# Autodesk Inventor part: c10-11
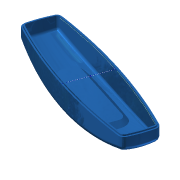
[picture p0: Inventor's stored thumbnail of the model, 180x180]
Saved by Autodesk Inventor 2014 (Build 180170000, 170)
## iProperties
Created: 2010-12
Part Number: c10-11
Material: Generic
Document SubType Name: Modeling
Designer: Thom Tremblay
Density: 1 g/cm^3
Appearance: Generic
Author: Thom Tremblay
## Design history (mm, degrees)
sketch "Sketch1"
  geometry: L1 (-60, -12)-(60, -12); L2 (60, -12)-(60, 12); L3 (60, 12)-(-60, 12); L4 (-60, 12)-(-60, -12); A1 r 350 centre (0, -332.819) between (60, 12) and (-60, 12); A2 r 350 centre (0, 332.819) between (-60, -12) and (60, -12); 3 further points
  constraints: 8 end point, 4 point on circle, 2 centre point, 2 midpoint, 2 parallel, 1 equal radius, 1 horizontal, 1 horizontal alignment, 1 perpendicular, 1 vertical alignment
  dimensions: "d0" = 120 distance of L3.end L2.end; "d1" = 24 distance of L2.end L1.end; "d2" = 350 radius of A1
workplane "Work Plane4"
sketch "Sketch5"
  geometry: L1 (-60, 12)-(-60, -12) reference; L2 (60, -12)-(60, 12) reference; L3 (-58, 10.314)-(-58, -10.314); L4 (58, -10.314)-(58, 10.314); A1 r 350 centre (0, 332.819) between (-60, -12) and (60, -12) reference; A2 r 350 centre (0, -332.819) between (60, 12) and (-60, 12) reference; A3 r 348 centre (0, 332.819) between (-58, -10.314) and (58, -10.314); A4 r 348 centre (0, -332.819) between (58, 10.314) and (-58, 10.314); 1 further point
  constraints: 4 end point, 4 point on circle, 2 centre point, 3 other
  dimensions: "d37" = 2 distance between parallel lines of L2 L4
sketch "Sketch6"
  geometry: L1 (-60, 0)-(60, 0); L2 (60, 0)-(58.843, 22.085); L3 (-60, 0)-(-58.779, 23.307); A1 r 691.758 centre (630.81, -36.204) between (-60, 0) and (-58, -100); A2 r 691.758 centre (-630.81, -36.204) between (58, -100) and (60, 0); 1 further point
  constraints: 6 end point, 4 point on circle, 2 centre point, 2 tangent, 1 horizontal
  dimensions: "d53" = 87 deg angle of L1 L3; "d54" = 87 deg angle of L1 L2 (= d53)
sketch "Sketch7"
  geometry: L1 (17.181, 0)-(12, 0) reference; L2 (15.181, -100)-(10.314, -100) reference; L3 (17.181, 0)-(16.768, 11.838); A1 r 911.322 centre (-893.585, -31.805) between (15.181, -100) and (17.181, 0); 1 further point
  constraints: 2 end point, 2 point on circle, 1 centre point, 1 tangent
  dimensions: "d56" = 88 deg angle of L1 L3
feature "LoftSrf2" sketch "Sketch5", "Sketch6", "Sketch7" dims "d57" = 0, "d58" = 90 deg, "d59" = 0, "d60" = 90 deg, "d61" = 0, "d62" = 90 deg, "d63" = 0, "d64" = 90 deg, "d65" = 0, "d66" = 90 deg
sketch "Sketch2"
  geometry: L1 (-75, -16)-(75, -16); L2 (-75, -60)-(75, -60); A1 r 183.781 centre (0, -183.781) between (75, -16) and (-75, -16); 2 further points
  constraints: 4 end point, 3 point on circle, 1 centre point, 1 coincident, 1 horizontal, 1 parallel
  dimensions: "d5" = 16 distance from line of point (0, 0) L1; "d7" = 60 distance from line of point (0, 0) L2; "d55" = 150 distance of L1.start L1.end
feature "RevolutionSrf1" sketch "Sketch2" dims angle "d8" = 40 deg
patch "Boundary Patch1" dims "d13" = 0, "d67" = 0, "d68" = 0, "d69" = 0, "d70" = 0
workplane "Work Plane1"
sketch "Sketch3"
  geometry: L1 (52, -85)-(52, -73); L2 (38, -73)-(38, -85); A1 r 7 centre (45, -73) between (52, -73) and (38, -73); A2 r 7 centre (45, -85) between (38, -85) and (52, -85); 1 further point
  constraints: 4 end point, 4 point on circle, 4 tangent, 2 centre point, 1 parallel, 1 vertical
  dimensions: "d15" = 12 distance of L1.start L1.end; "d16" = 7 radius of A1; "d50" = 45 horizontal distance of A1.centre point (0, 0); "d51" = 85 vertical distance of point (0, 0) A2.centre
extrude_surface "ExtrusionSrf2" sketch "Sketch3" dims "d19" = 14, "d20" = 5 deg
pattern_linear "Rectangular Pattern1" dims "d23" = 90
workplane "Work Plane2"
feature "Sculpt1"
sketch "Sketch4"
  geometry: L1 (-24.5, 6)-(24.5, 6); L2 (27.5, 3)-(27.5, -3); L3 (24.5, -6)-(-24.5, -6); L4 (-27.5, -3)-(-27.5, 3); A1 r 3 centre (-24.5, 3) between (-24.5, 6) and (-27.5, 3); A2 r 3 centre (24.5, 3) between (27.5, 3) and (24.5, 6); A3 r 3 centre (24.5, -3) between (24.5, -6) and (27.5, -3); A4 r 3 centre (-24.5, -3) between (-27.5, -3) and (-24.5, -6); 6 further points
  constraints: 8 end point, 8 point on circle, 8 tangent, 6 point on line, 4 centre point, 3 equal radius, 2 midpoint, 2 parallel, 1 horizontal, 1 horizontal alignment, 1 perpendicular, 1 vertical alignment
  dimensions: "d28" = 55 distance of point (27.5, -6) point (-27.5, -6); "d29" = 12 distance of point (27.5, 6) point (27.5, -6); "d30" = 3 radius of A1
extrude_surface "ExtrusionSrf6" sketch "Sketch4" dims "d31" = 14, "d32" = 45 deg
patch "Boundary Patch2" dims "d33" = 0, "d34" = 0
fillet "Fillet1" dims "d79" = 4, "d80" = 3, "d81" = 1
feature "Sculpt2"
node "Splitting Plane 1"
shell "Shell1" dims "d83" = 2
split "Split1"
  body "Solid1"
feature "Lip1" dims "d188" = 1, "d189" = 1, "d190" = 0, "d191" = 0, "d192" = 0, "d193" = 0
feature "Lip2" dims "d194" = 1, "d195" = 1, "d196" = 0, "d197" = 0, "d198" = 0, "d199" = 0.5
split "Split3"
  node "Back"
sketch "Sketch9"
  geometry: L1 (50.167, -73)-(50.167, -85) reference; L2 (39.833, -85)-(39.833, -73) reference; L3 (45, -73)-(45, -85); L4 (45, -85)-(39.833, -85); A1 r 5.167 centre (45, -73) between (50.167, -73) and (39.833, -73) reference; A2 r 5.167 centre (45, -85) between (39.833, -85) and (50.167, -85) reference; 5 further points
  constraints: 4 end point, 1 horizontal, 1 midpoint, 1 parallel, 1 perpendicular, 1 vertical, 3 other
  dimensions: "d86" = 90 distance of point (45, -79) point (-45, -79); "d89" = 40 distance of point (45, -79) point (45, -39)
  node "Projected Loop1"
feature "Boss1" dims "d92" = 0, "d93" = 0, "d94" = 7, "d95" = 2, "d96" = 0.5, "d97" = 6, "d98" = 1.25, "d99" = 3.5, "d100" = 2.5 deg, "d101" = 2.5 deg, "d102" = 2.5 deg, "d103" = 2.5 deg, "d104" = 90 deg, "d107" = 2, "d108" = 2, "d109" = 10, "d110" = 0, "d111" = 10 deg, "d112" = 2.5 deg, "d113" = 0, "d114" = 0, "d115" = 0, "d116" = 360 deg
feature "Boss2" dims "d117" = 3, "d118" = 0, "d119" = 6, "d120" = 3, "d121" = 9.5, "d122" = 2 deg, "d123" = 1 deg, "d126" = 2, "d127" = 2, "d128" = 10, "d129" = 0, "d130" = 10 deg, "d131" = 2.5 deg, "d132" = 0, "d133" = 0, "d134" = 0, "d135" = 360 deg
workplane "Work Plane6"
sketch "Sketch10"
  geometry: L1 (24, -85)-(-24, -85); L2 (-30, -79)-(-30, -51); L3 (-24, -45)-(24, -45); L4 (30, -51)-(30, -79); L5 (54.344, -100)-(-54.344, -100) reference; A1 r 6 centre (-24, -51) between (-24, -45) and (-30, -51); A2 r 6 centre (24, -51) between (30, -51) and (24, -45); A3 r 6 centre (24, -79) between (24, -85) and (30, -79); A4 r 6 centre (-24, -79) between (-30, -79) and (-24, -85); 5 further points
  constraints: 8 end point, 8 point on circle, 8 tangent, 6 point on line, 4 centre point, 3 equal radius, 2 parallel, 1 horizontal, 1 midpoint, 1 perpendicular, 1 vertical alignment
  dimensions: "d137" = 60 distance of point (-30, -45) point (30, -45); "d138" = 40 distance of point (-30, -85) point (-30, -45); "d139" = 15 distance between parallel lines of L5 L1; "d141" = 6 radius of A2
feature "Rest1" sketch "Sketch10" dims "d142" = 5, "d143" = 0, "d144" = 0, "d145" = 0, "d146" = 2 deg, "d147" = 2 deg, "d148" = 2
feature "Rule Fillet1" dims "d149" = 2, "d150" = 1
workplane "Work Plane7"
sketch "Sketch11" dims "d154" = 16, "d155" = 8, "d161" = 10, "d168" = 10
  geometry: L1 (-13, -39.858)-(-13, -90.142); L2 (-25.187, -85)-(29.449, -85); L3 (0, -39.858)-(0, -90.142); L4 (13, -39.858)-(13, -90.142); L5 (-25.187, -77)-(29.449, -77); L6 (-25.187, -69)-(29.449, -69); L7 (-25.187, -61)-(29.449, -61); L8 (-25.187, -53)-(29.449, -53); L9 (-25.187, -45)-(29.449, -45); C1 r 22.5 at (0, -65); 3 further points; 1 other entity
  constraints: 18 end point, 2 coincident, 2 vertical, 1 centre point, 1 horizontal, 1 midpoint, 1 perpendicular, 1 vertical alignment, 23 other
  dimensions: "d152" = 45 diameter of C1; "d153" = 65 distance of point (0, 0) C1.centre; "d158" = 13 distance of L1.start L3.start; "d165" = 8 distance of L2.start L5.start; "d170" = 4 distance from line of L7 point (0, -65)
feature "Grill1" sketch "Sketch11" dims "d173" = 2, "d174" = 0, "d175" = 1, "d176" = 2, "d177" = 0, "d178" = 1, "d179" = 0.5, "d180" = 0, "d181" = 2, "d182" = 1, "d183" = 2 deg, "d184" = 0, "d185" = 88.84492
sketch "Sketch12"
  geometry: L1 (-12.481, -61.203)-(12.401, -61.203); L2 (12.401, -61.203)-(12.401, -68.714); L3 (12.401, -68.714)-(-12.481, -68.714); L4 (-12.481, -68.714)-(-12.481, -61.203); 1 further point
  constraints: 2 other
emboss "Emboss1" sketch "Sketch12" dims "d0" = 120, "d1" = 24, "d2" = 350, "d186" = 0.5, "d187" = 0
sketch "Sketch13"
  geometry: L1 (0, 15.66)-(0, -14.781); 6 further points
  constraints: 2 end point, 1 coincident, 1 point on line, 1 vertical, 4 other
body "Srf2"
body "Srf3"
body "Srf4"
body "Srf5"
body "Srf6"
body "Srf7"
body "Srf8"
body "Srf9"
body "Srf11"
feature "Stitch Surface1"
body "Srf12"
extrude_surface "ExtrusionSrf3"
extrude_surface "ExtrusionSrf4"
extrude_surface "ExtrusionSrf5"
node "Front"
node "Back - Top"
node "Back - Bottom"
other parameters: "d14" = -24, "d52" = -6, "d171" = 1, "d172" = 2
